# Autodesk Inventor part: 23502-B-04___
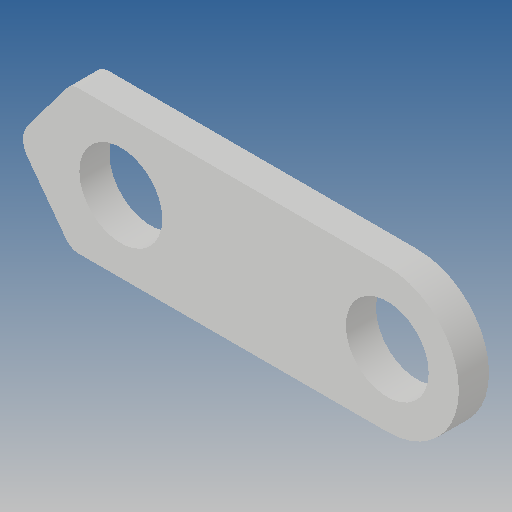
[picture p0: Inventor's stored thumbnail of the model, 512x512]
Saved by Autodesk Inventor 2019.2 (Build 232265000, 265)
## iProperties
Created: 2010-06
Part Number: 23502-B-04___
Material: Ogólny
Document SubType Name: Modeling
Designer: CADENGINEERING4
Density: 1 g/cm^3
Appearance: Domyślna
Author: CADENGINEERING4
Revision Number: ANY
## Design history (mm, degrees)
feature "NONE"
node "Bryła1"
